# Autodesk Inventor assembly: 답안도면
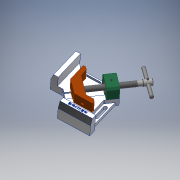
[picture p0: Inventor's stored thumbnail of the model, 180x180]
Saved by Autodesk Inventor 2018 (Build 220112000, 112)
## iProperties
Created: 2020-05
Part Number: 답안도면
Document SubType Name: Assembly
Designer: theplan76
Author: theplan76
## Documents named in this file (11)
- C:\Users\theplan76\Desktop\700506v1057\답안도면.iam
- C:\Users\theplan76\Desktop\700506v1057\베이스.ipt
- C:\Users\theplan76\Desktop\700506v1057\멈춤나사 M4x5.ipt
- C:\Users\theplan76\Desktop\700506v1057\멈춤나사 M4x10.ipt
- C:\Users\theplan76\Desktop\700506v1057\볼트 M4x16.ipt
- C:\Users\theplan76\Desktop\700506v1057\부시.ipt
- C:\Users\theplan76\Desktop\700506v1057\서포트.ipt
- C:\Users\theplan76\Desktop\700506v1057\조.ipt
- C:\Users\theplan76\Desktop\700506v1057\평행 핀 2.5x24.ipt
- C:\Users\theplan76\Desktop\700506v1057\핸들.ipt
- C:\Users\theplan76\Desktop\700506v1057\리드스크류.ipt
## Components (1 placed, 1 different names)
1. 핸들:1
